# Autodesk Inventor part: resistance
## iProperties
Author: chr
Created: 2001-06
Part Number: resistance
Material: Par défaut
Document SubType Name: Modélisation
Designer: chr
Control State: 0
Master: False
Checked Out: False
PropertySet Name: Design Tracking Control
Shininess: 41.0
PropertySet Name: _Private Model Information
Length Units: 11269
Angle Units: 11286
Time Units: 11279
Mass Units: 11290
Length Display Precision: 3
Angle Display Precision: 2
Compacted: False
Density: 0.0
Volumn: 0.0
Area: 0.0
PropertySet Name: Model Information
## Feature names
1. Extrusion1
2. Balayage1
3. Symétrie1 [Mirror]
